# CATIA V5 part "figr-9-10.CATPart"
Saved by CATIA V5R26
Part number: Part1
Bounding box of the stored display mesh (mm): x -15.705 to 98.193, y 0 to 272.268, z -20.723 to 20.723
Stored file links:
  D:\_Deepak\CATIA\CATIA V5-6R2016_Deepak\Resources\Part files\Partfiles\c09_catia_v5_6r2016_prt\figr-9-10.CATPart
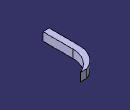
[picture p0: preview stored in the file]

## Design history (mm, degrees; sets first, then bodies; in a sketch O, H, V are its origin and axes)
Body1 (main body)
  Sketch1 on xy-plane, origin (0, 0, 0), H (1, 0, 0), V (0, 1, 0)
    line L1 (0, 0) -> (0, 150)
    arc A1 centre (131.8599, 150) radius 131.8599 from (0, 150) to (82.4884, 272.2681) cw
    length L1 = 150
    tangency: A1 L1
  Sketch2 on zx-plane, origin (0, 0, 0), H (-1, 0, 0), V (0, 0, 1)
    line L1 (15.7048, 20.7231) -> (15.7048, -20.7231)
    line L2 (15.7048, -20.7231) -> (-15.7048, -20.7231)
    line L3 (-15.7048, -20.7231) -> (-15.7048, 20.7231)
    line L4 (-15.7048, 20.7231) -> (15.7048, 20.7231)
    vertical: L1 V, L3 V
    horizontal: L2 H, L4 H
    equidistance: L1 L3 O, L2 L4 O
  Rib1: profile Sketch2, centre curve Sketch1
